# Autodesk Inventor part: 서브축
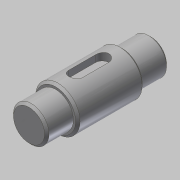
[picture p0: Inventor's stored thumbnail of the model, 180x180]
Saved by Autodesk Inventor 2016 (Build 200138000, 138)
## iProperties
Created: 2019-03
Part Number: 서브축
Material: 강철, 연강
Document SubType Name: Modeling
Designer: mduedu
Density: 1 g/cm^3
Appearance: 강철
Author: mduedu
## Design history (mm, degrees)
sketch "스케치1"
  geometry: L1 (0, 0)-(12, 0); L2 (12, 0)-(12, 8); L3 (12, 8)-(0, 8); L4 (0, 8)-(0, 0); L5 (12, 0)-(42, 0); L6 (42, 0)-(42, 10); L7 (42, 10)-(12, 10); L8 (12, 10)-(12, 0); L9 (42, 0)-(55, 0); L10 (55, 0)-(55, 8); L11 (55, 8)-(42, 8); L12 (42, 8)-(42, 0)
  constraints: 24 end point, 6 parallel, 3 horizontal, 3 perpendicular
  dimensions: "d0" = 16 diameter of L3 L1; "d2" = 20 diameter of L7 L5; "d3" = 16 diameter of L11 L9; "d4" = 12 distance of L2.end L3.end; "d5" = 30 distance of L6.end L7.end; "d6" = 55 distance between parallel lines of L10 L4
revolve "회전1" sketch "스케치1" stored, may be unused: angle "d7" = 90 deg
node "작업 평면1"
sketch "스케치2" dims "d10" = 18
  geometry: L1 (6, -3)-(-6, -3); L2 (-6, -3)-(-6, 3); L3 (-6, 3)-(6, 3); L4 (6, 3)-(6, -3); L5 (15, 10)-(15, -10) reference; 3 further points
  constraints: 8 end point, 2 midpoint, 2 parallel, 2 vertical alignment, 1 horizontal, 1 horizontal alignment, 1 perpendicular, 4 other
  dimensions: "d8" = 6 distance between parallel lines of L3 L1; "d11" = 6 dimension on L5
extrude "돌출1" cut sketch "스케치2" distance "d12" = 3.5; taper "d13" = 0 deg
chamfer "모따기1" distance "d14" = 1; stored, may be unused: second distance "d15" = 2, angle "d16" = 45 deg
chamfer "모따기2" distance "d17" = 1; stored, may be unused: second distance "d18" = 2, angle "d19" = 45 deg
node "솔리드1"
